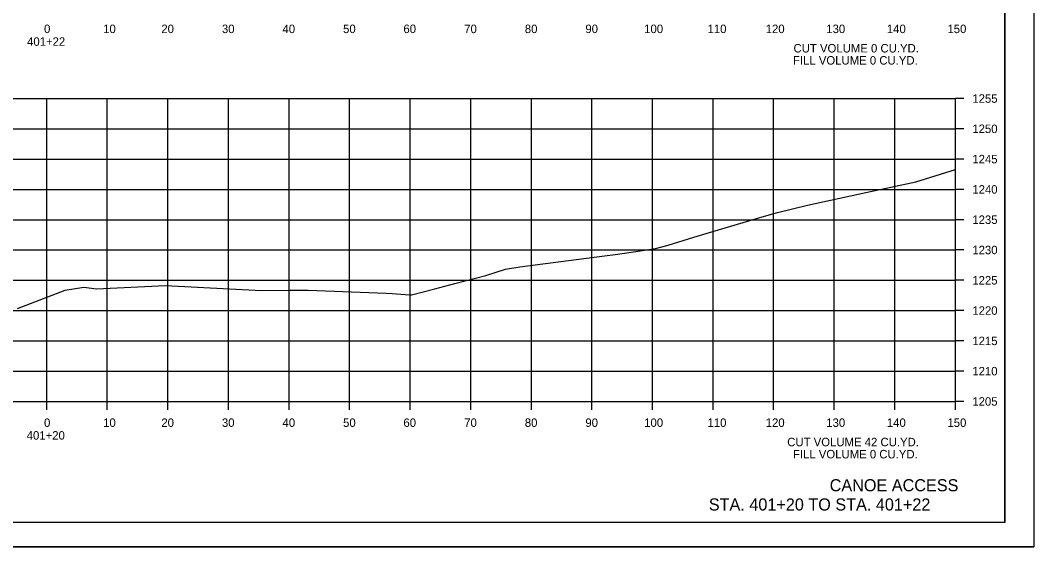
# Model space of a CAD drawing. Extents: x 1406028 to 1412453, y 321733 to 325986.
# Drawn here: x 1411778.9 to 1411946.2, y 322898.3 to 322985.2 of the extents above; entities that cross this region are included whole.
import ezdxf

# ---------------------------------------------------------------- set-up
doc = ezdxf.new("R2010")
doc.units = 0
for name, color, linetype in [('R_Axis', 7, 'Continuous'), ('R_Axis Annot', 7, 'Continuous'), ('R_Border', 7, 'Continuous'), ('R_Draft', 7, 'Continuous'), ('R_Exist Surface', 7, 'Continuous'), ('R_Grid', 7, 'Continuous'), ('R_No Plot', 7, 'Continuous')]:
    doc.layers.add(name, color=color, linetype=linetype)

msp = doc.modelspace()

# ---------------------------------------------------------------- linework, layer by layer
at = {"layer": 'R_Axis'}
for p, q in [((1411933.24, 322922.26), (1411933.24, 322972.26)), ((1411934.64, 322972.26), (1411933.24, 322972.26)), ((1411934.64, 322967.26), (1411933.24, 322967.26)), ((1411934.64, 322962.26), (1411933.24, 322962.26)), ((1411934.64, 322957.26), (1411933.24, 322957.26)), ((1411934.64, 322952.26), (1411933.24, 322952.26)), ((1411934.64, 322947.26), (1411933.24, 322947.26)), ((1411934.64, 322942.26), (1411933.24, 322942.26)), ((1411934.64, 322937.26), (1411933.24, 322937.26)), ((1411934.64, 322932.26), (1411933.24, 322932.26)), ((1411934.64, 322927.26), (1411933.24, 322927.26)), ((1411633.24, 322922.26), (1411933.24, 322922.26)), ((1411783.24, 322920.86), (1411783.24, 322922.26)), ((1411793.24, 322920.86), (1411793.24, 322922.26)), ((1411803.24, 322920.86), (1411803.24, 322922.26)), ((1411813.24, 322920.86), (1411813.24, 322922.26)), ((1411823.24, 322920.86), (1411823.24, 322922.26)), ((1411833.24, 322920.86), (1411833.24, 322922.26)), ((1411843.24, 322920.86), (1411843.24, 322922.26)), ((1411853.24, 322920.86), (1411853.24, 322922.26)), ((1411863.24, 322920.86), (1411863.24, 322922.26)), ((1411873.24, 322920.86), (1411873.24, 322922.26)), ((1411883.24, 322920.86), (1411883.24, 322922.26)), ((1411893.24, 322920.86), (1411893.24, 322922.26)), ((1411903.24, 322920.86), (1411903.24, 322922.26)), ((1411913.24, 322920.86), (1411913.24, 322922.26)), ((1411923.24, 322920.86), (1411923.24, 322922.26)), ((1411933.24, 322920.86), (1411933.24, 322922.26)), ((1411934.64, 322922.26), (1411933.24, 322922.26))]:
    msp.add_line(p, q, dxfattribs=at)
at = {"layer": 'R_Border'}
for q in [(1411941.42, 323107.72), (1411625.24, 322902.26)]:
    msp.add_line((1411941.42, 322902.26), q, dxfattribs=at)
at = {"layer": 'R_Exist Surface'}
msp.add_lwpolyline([(1411778.43, 322937.58), (1411786.26, 322940.63), (1411789.35, 322941.11), (1411791.47, 322940.87), (1411802.86, 322941.4), (1411818.71, 322940.58), (1411823.2, 322940.62), (1411826.39, 322940.64), (1411839.26, 322940.11), (1411840.26, 322940.08), (1411843.1, 322939.88), (1411843.45, 322939.85), (1411847.32, 322940.87), (1411850.61, 322941.74), (1411855.75, 322943.05), (1411858.97, 322944.09), (1411861.33, 322944.47), (1411869.37, 322945.53), (1411875.29, 322946.27), (1411877.08, 322946.53), (1411880.48, 322947), (1411883.74, 322947.52), (1411885.8, 322948.06), (1411890.08, 322949.39), (1411901.32, 322952.71), (1411903.89, 322953.47), (1411908.81, 322954.68), (1411918.45, 322956.75), (1411926.69, 322958.52), (1411933.24, 322960.53)], dxfattribs=at)
at = {"layer": 'R_Grid'}
for p, q in [((1411633.24, 322972.26), (1411933.24, 322972.26)), ((1411783.24, 322922.26), (1411783.24, 322972.26)), ((1411793.24, 322922.26), (1411793.24, 322972.26)), ((1411803.24, 322922.26), (1411803.24, 322972.26)), ((1411813.24, 322922.26), (1411813.24, 322972.26)), ((1411823.24, 322922.26), (1411823.24, 322972.26)), ((1411833.24, 322922.26), (1411833.24, 322972.26)), ((1411843.24, 322922.26), (1411843.24, 322972.26)), ((1411853.24, 322922.26), (1411853.24, 322972.26)), ((1411863.24, 322922.26), (1411863.24, 322972.26)), ((1411873.24, 322922.26), (1411873.24, 322972.26)), ((1411883.24, 322922.26), (1411883.24, 322972.26)), ((1411893.24, 322922.26), (1411893.24, 322972.26)), ((1411903.24, 322922.26), (1411903.24, 322972.26)), ((1411913.24, 322922.26), (1411913.24, 322972.26)), ((1411923.24, 322922.26), (1411923.24, 322972.26)), ((1411933.24, 322922.26), (1411933.24, 322972.26)), ((1411633.24, 322967.26), (1411933.24, 322967.26)), ((1411633.24, 322962.26), (1411933.24, 322962.26)), ((1411633.24, 322957.26), (1411933.24, 322957.26)), ((1411633.24, 322952.26), (1411933.24, 322952.26)), ((1411633.24, 322947.26), (1411933.24, 322947.26)), ((1411633.24, 322942.26), (1411933.24, 322942.26)), ((1411633.24, 322937.26), (1411933.24, 322937.26)), ((1411633.24, 322932.26), (1411933.24, 322932.26)), ((1411633.24, 322927.26), (1411933.24, 322927.26)), ((1411633.24, 322922.26), (1411933.24, 322922.26))]:
    msp.add_line(p, q, dxfattribs=at)
at = {"layer": 'R_No Plot'}
msp.add_line((1411612.84, 322898.29), (1411946.18, 322898.29), dxfattribs=at)
for points in [[(1411612.84, 323111.62), (1411946.18, 323111.62), (1411946.18, 322898.28), (1411612.84, 322898.28)], [(1411859.16, 323107.72), (1411878.78, 323107.72), (1411878.78, 323097.84), (1411894.9, 323097.84), (1411918.1, 323097.84), (1411918.1, 323073.51), (1411941.42, 323073.51), (1411941.42, 322902.26), (1411625.24, 322902.26), (1411625.24, 323107.72)]]:
    msp.add_lwpolyline(points, close=True, dxfattribs=at)

# ---------------------------------------------------------------- texts
at = {"layer": 'R_Axis Annot'}
for s, p in [('0', (1411782.79, 322983.06)), ('10', (1411792.55, 322983.06)), ('20', (1411802.16, 322983.06)), ('30', (1411812.16, 322983.06)), ('40', (1411822.16, 322983.06)), ('50', (1411832.16, 322983.06)), ('60', (1411842.12, 322983.06)), ('70', (1411852.16, 322983.06)), ('80', (1411862.16, 322983.06)), ('90', (1411872.16, 322983.06)), ('100', (1411881.87, 322983.06)), ('110', (1411892.32, 322983.06)), ('120', (1411901.93, 322983.06)), ('130', (1411911.93, 322983.06)), ('140', (1411921.93, 322983.06)), ('150', (1411931.93, 322983.06)), ('401+22', (1411779.99, 322980.96)), ('CUT VOLUME 0 CU.YD.', (1411906.52, 322979.86)), ('FILL VOLUME 0 CU.YD.', (1411906.43, 322977.86)), ('1255', (1411936.04, 322971.56)), ('1250', (1411936.04, 322966.56)), ('1245', (1411936.04, 322961.56)), ('1240', (1411936.04, 322956.56)), ('1235', (1411936.04, 322951.56)), ('1230', (1411936.04, 322946.56)), ('1225', (1411936.04, 322941.56)), ('1220', (1411936.04, 322936.56)), ('1215', (1411936.04, 322931.56)), ('1210', (1411936.04, 322926.56)), ('1205', (1411936.04, 322921.56)), ('0', (1411782.79, 322918.06)), ('10', (1411792.55, 322918.06)), ('20', (1411802.16, 322918.06)), ('30', (1411812.16, 322918.06)), ('40', (1411822.16, 322918.06)), ('50', (1411832.16, 322918.06)), ('60', (1411842.12, 322918.06)), ('70', (1411852.16, 322918.06)), ('80', (1411862.16, 322918.06)), ('90', (1411872.16, 322918.06)), ('100', (1411881.87, 322918.06)), ('110', (1411892.32, 322918.06)), ('120', (1411901.93, 322918.06)), ('130', (1411911.93, 322918.06)), ('140', (1411921.93, 322918.06)), ('150', (1411931.93, 322918.06)), ('401+20', (1411779.93, 322915.96)), ('CUT VOLUME 42 CU.YD.', (1411905.48, 322914.86)), ('FILL VOLUME 0 CU.YD.', (1411906.43, 322912.86))]:
    msp.add_text(s, height=1.4, dxfattribs=at).set_placement(p)
at = {"layer": 'R_Draft'}
for s, p in [('CANOE ACCESS', (1411912.49, 322907.43)), ('STA. 401+20 TO STA. 401+22', (1411892.54, 322904.26))]:
    msp.add_text(s, height=2, dxfattribs=at).set_placement(p)

doc.saveas('drawing.dxf')
